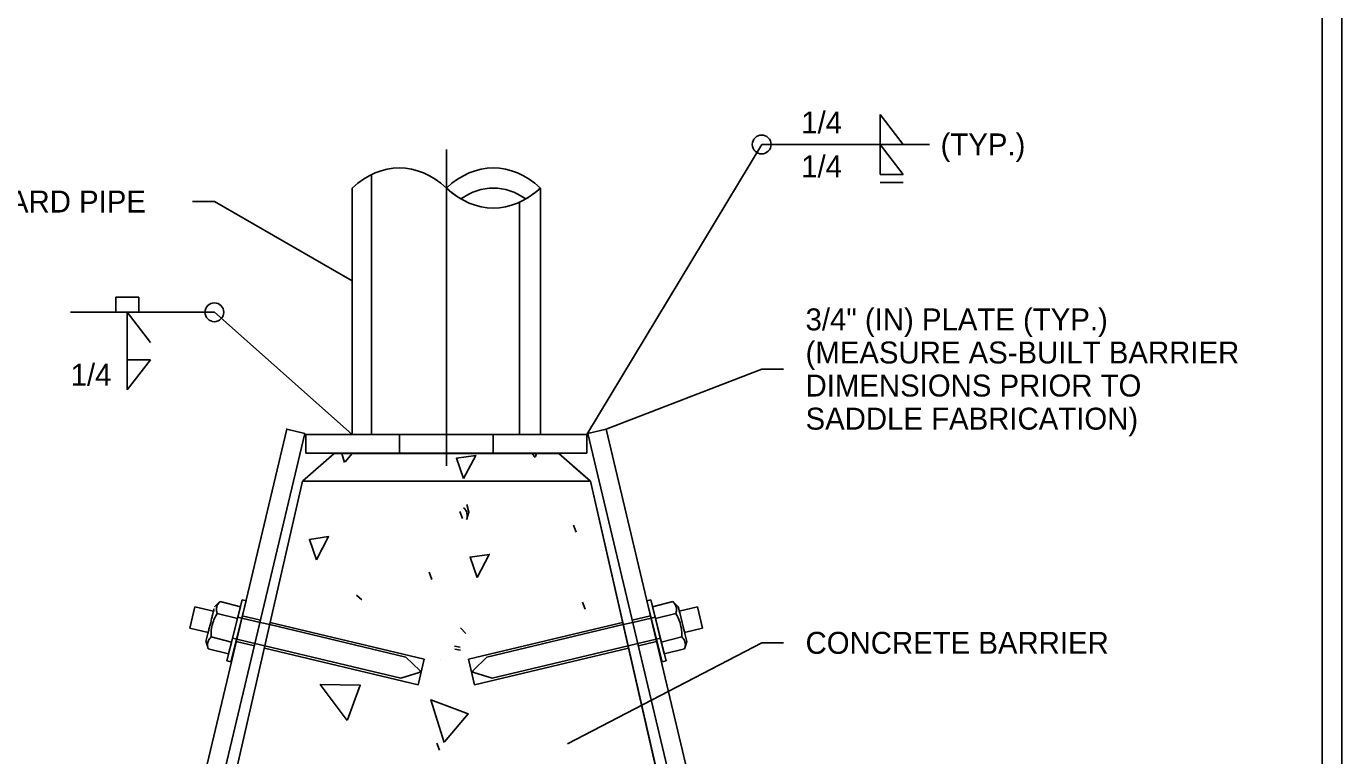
# Model space of a CAD drawing. Extents: x 99988 to 100172, y 99995 to 100047.
# Drawn here: x 100031.616 to 100035.812, y 100003.415 to 100005.742 of the extents above; entities that cross this region are included whole.
import ezdxf

# ---------------------------------------------------------------- set-up
doc = ezdxf.new("R2010")
doc.units = 0
for name, color, linetype in [('Level 1', 7, 'Continuous'), ('Level 10', 7, 'Continuous'), ('Level 12', 7, 'Continuous'), ('Level 15', 7, 'Continuous'), ('Level 18', 7, 'Continuous'), ('Level 20', 7, 'Continuous'), ('Level 24', 7, 'Continuous'), ('Level 51', 7, 'Continuous'), ('Level 8', 7, 'Continuous'), ('SH_GI_PlotLimits', 7, 'Continuous'), ('SH_GI_SheetBorder', 7, 'Continuous'), ('SH_RS_ConstructionNoteFlag', 7, 'Continuous'), ('SH_RS_DimensionLines', 7, 'Continuous')]:
    doc.layers.add(name, color=color, linetype=linetype)

msp = doc.modelspace()

# ---------------------------------------------------------------- linework, layer by layer
at = {"layer": 'Level 1'}
for p, q in [((100033.9621, 100005.3648), (100034.4979, 100005.3648)), ((100034.3401, 100005.2689), (100034.4138, 100005.2689)), ((100034.3401, 100005.2439), (100034.4138, 100005.2439)), ((100032.216, 100004.8293), (100031.7575, 100004.8293))]:
    msp.add_line(p, q, dxfattribs=at)
for centre in [(100033.9621, 100005.3648), (100032.216, 100004.8293)]:
    msp.add_circle(centre, 0.03, dxfattribs=at)
at = {"layer": 'Level 10'}
for p, q in [((100033.028, 100004.1913), (100033.0217, 100004.2164)), ((100032.234, 100003.9067), (100032.2168, 100003.8895)), ((100032.2992, 100003.8902), (100032.2342, 100003.9064)), ((100032.3048, 100003.9125), (100032.2559, 100003.7172)), ((100032.2685, 100003.714), (100032.3174, 100003.9093)), ((100032.2992, 100003.8902), (100032.2897, 100003.8523)), ((100032.299, 100003.8904), (100032.2989, 100003.8902)), ((100032.3174, 100003.9093), (100032.3048, 100003.9125)), ((100033.5954, 100003.9093), (100033.608, 100003.9125)), ((100033.6443, 100003.714), (100033.5954, 100003.9093)), ((100033.608, 100003.9125), (100033.6569, 100003.7172)), ((100033.6136, 100003.8902), (100033.6786, 100003.9064)), ((100033.6136, 100003.8902), (100033.6231, 100003.8523)), ((100033.6138, 100003.8904), (100033.6139, 100003.8902)), ((100033.6788, 100003.9067), (100033.696, 100003.8895)), ((100032.2897, 100003.8523), (100032.2247, 100003.8686)), ((100032.2707, 100003.7764), (100032.2898, 100003.8528)), ((100032.2897, 100003.8523), (100032.2709, 100003.7773)), ((100032.3052, 100003.8608), (100032.3634, 100003.8469)), ((100032.3942, 100003.8396), (100032.8859, 100003.7227)), ((100033.5186, 100003.8396), (100033.0269, 100003.7227)), ((100033.6076, 100003.8608), (100033.5494, 100003.8469)), ((100033.6421, 100003.7764), (100033.623, 100003.8528)), ((100033.6231, 100003.8523), (100033.6881, 100003.8686)), ((100033.6231, 100003.8523), (100033.6419, 100003.7773)), ((100032.1892, 100003.7792), (100032.1955, 100003.8044)), ((100033.0014, 100003.8222), (100033.0187, 100003.805)), ((100033.7236, 100003.7792), (100033.7174, 100003.8044)), ((100032.2615, 100003.7395), (100032.1965, 100003.7558)), ((100032.2709, 100003.7773), (100032.2059, 100003.7936)), ((100032.2709, 100003.7773), (100032.2615, 100003.7395)), ((100032.2615, 100003.7395), (100032.2707, 100003.7764)), ((100032.2859, 100003.7793), (100032.344, 100003.7655)), ((100032.3755, 100003.758), (100032.8665, 100003.6413)), ((100033.5373, 100003.758), (100033.0463, 100003.6413)), ((100033.6269, 100003.7793), (100033.5688, 100003.7655)), ((100033.6419, 100003.7773), (100033.7069, 100003.7936)), ((100033.6419, 100003.7773), (100033.6514, 100003.7395)), ((100033.6514, 100003.7395), (100033.6421, 100003.7764)), ((100033.6514, 100003.7395), (100033.7163, 100003.7558)), ((100032.2559, 100003.7172), (100032.2685, 100003.714)), ((100032.8859, 100003.7227), (100032.8665, 100003.6413)), ((100032.9365, 100003.7209), (100032.9365, 100003.7207)), ((100033.0269, 100003.7227), (100033.0463, 100003.6413)), ((100033.6569, 100003.7172), (100033.6443, 100003.714))]:
    msp.add_line(p, q, dxfattribs=at)
for points, degree in [([(100033.0207, 100004.1678), (100033.0229, 100004.1749), (100033.0237, 100004.1818), (100033.0205, 100004.1947), (100033.0165, 100004.2004), (100033.0112, 100004.2056)], 3), ([(100033.0207, 100004.1678), (100033.0229, 100004.1749), (100033.0237, 100004.1818), (100033.0205, 100004.1947), (100033.0165, 100004.2004), (100033.0112, 100004.2056)], 3), ([(100033.021, 100004.1684), (100033.0233, 100004.176), (100033.0257, 100004.1836), (100033.028, 100004.1913)], 2), ([(100032.1955, 100003.8044), (100032.1955, 100003.8044), (100032.2141, 100003.8789), (100032.2168, 100003.8895), (100032.2141, 100003.8789), (100032.1955, 100003.8044), (100032.1955, 100003.8044)], 4), ([(100032.2247, 100003.8686), (100032.2226, 100003.8757), (100032.2218, 100003.8826), (100032.225, 100003.8955), (100032.229, 100003.9012), (100032.2342, 100003.9064)], 3), ([(100032.2247, 100003.8686), (100032.2226, 100003.8757), (100032.2218, 100003.8826), (100032.225, 100003.8955), (100032.229, 100003.9012), (100032.2342, 100003.9064)], 3), ([(100033.6881, 100003.8686), (100033.6902, 100003.8757), (100033.6911, 100003.8826), (100033.6878, 100003.8955), (100033.6838, 100003.9012), (100033.6786, 100003.9064)], 3), ([(100033.6881, 100003.8686), (100033.6902, 100003.8757), (100033.6911, 100003.8826), (100033.6878, 100003.8955), (100033.6838, 100003.9012), (100033.6786, 100003.9064)], 3), ([(100033.7174, 100003.8044), (100033.7174, 100003.8044), (100033.7093, 100003.837), (100033.696, 100003.8895)], 3), ([(100032.2059, 100003.7936), (100032.2053, 100003.8068), (100032.2061, 100003.8198), (100032.2125, 100003.8453), (100032.218, 100003.8573), (100032.2247, 100003.8686)], 3), ([(100033.7069, 100003.7936), (100033.7075, 100003.8068), (100033.7067, 100003.8198), (100033.7003, 100003.8453), (100033.6948, 100003.8573), (100033.6881, 100003.8686)], 3), ([(100032.1962, 100003.7563), (100032.1939, 100003.764), (100032.1915, 100003.7716), (100032.1892, 100003.7792)], 2), ([(100032.1965, 100003.7558), (100032.1943, 100003.7629), (100032.1935, 100003.7697), (100032.1967, 100003.7826), (100032.2007, 100003.7884), (100032.2059, 100003.7936)], 3), ([(100032.1965, 100003.7558), (100032.1943, 100003.7629), (100032.1935, 100003.7697), (100032.1967, 100003.7826), (100032.2007, 100003.7884), (100032.2059, 100003.7936)], 3), ([(100033.7163, 100003.7558), (100033.7185, 100003.7629), (100033.7193, 100003.7697), (100033.7161, 100003.7826), (100033.7121, 100003.7884), (100033.7069, 100003.7936)], 3), ([(100033.7163, 100003.7558), (100033.7185, 100003.7629), (100033.7193, 100003.7697), (100033.7161, 100003.7826), (100033.7121, 100003.7884), (100033.7069, 100003.7936)], 3), ([(100033.7166, 100003.7563), (100033.719, 100003.764), (100033.7213, 100003.7716), (100033.7236, 100003.7792)], 2)]:
    msp.add_open_spline(points, degree=degree, dxfattribs=at)
at = {"layer": 'Level 12'}
for p, q in [((100032.5083, 100004.4395), (100033.4041, 100004.4395)), ((100032.5083, 100004.3797), (100032.5083, 100004.4395)), ((100033.4041, 100004.4395), (100033.4041, 100004.3797)), ((100033.4041, 100004.3797), (100032.5083, 100004.3797))]:
    msp.add_line(p, q, dxfattribs=at)
for points in [[(100032.5051, 100004.4431), (100032.0075, 100002.35), (100031.9493, 100002.3638), (100032.447, 100004.4569)], [(100033.4073, 100004.4431), (100033.9049, 100002.35), (100033.9631, 100002.3638), (100033.4655, 100004.4569)]]:
    msp.add_lwpolyline(points, close=True, dxfattribs=at)
at = {"layer": 'Level 15'}
for points in [[(100032.6562, 100004.93), (100032.216, 100005.1827), (100032.146, 100005.1827)], [(100033.4655, 100004.4569), (100033.9621, 100004.6483), (100034.0321, 100004.6483)], [(100033.3428, 100003.4522), (100033.9621, 100003.7748), (100034.0321, 100003.7748)]]:
    msp.add_lwpolyline(points, dxfattribs=at)
at = {"layer": 'Level 18'}
for p, q in [((100032.1542, 100003.8896), (100032.138, 100003.8218)), ((100032.2128, 100003.8757), (100032.1542, 100003.8896)), ((100033.6989, 100003.8754), (100033.7575, 100003.8894)), ((100033.7575, 100003.8894), (100033.7736, 100003.8215)), ((100032.2909, 100003.857), (100032.3036, 100003.854)), ((100032.3036, 100003.854), (100032.3618, 100003.8402)), ((100032.3618, 100003.8402), (100032.3926, 100003.8328)), ((100033.5202, 100003.8328), (100033.551, 100003.8402)), ((100033.6092, 100003.854), (100033.551, 100003.8402)), ((100033.6219, 100003.857), (100033.6092, 100003.854)), ((100032.138, 100003.8218), (100032.1958, 100003.808)), ((100032.3926, 100003.8328), (100032.827, 100003.7296)), ((100033.5202, 100003.8328), (100033.0858, 100003.7296)), ((100033.7736, 100003.8215), (100033.7158, 100003.8078)), ((100032.2739, 100003.7894), (100032.2875, 100003.7861)), ((100032.2875, 100003.7861), (100032.3456, 100003.7723)), ((100032.3456, 100003.7723), (100032.3771, 100003.7648)), ((100032.8109, 100003.6617), (100032.3771, 100003.7648)), ((100033.1019, 100003.6617), (100033.5357, 100003.7648)), ((100033.5357, 100003.7648), (100033.5672, 100003.7723)), ((100033.6253, 100003.7861), (100033.5672, 100003.7723)), ((100033.6389, 100003.7894), (100033.6253, 100003.7861)), ((100032.827, 100003.7296), (100032.8711, 100003.6869)), ((100033.0858, 100003.7296), (100033.0417, 100003.6869)), ((100032.8695, 100003.6799), (100032.8109, 100003.6617)), ((100033.0434, 100003.6799), (100033.1019, 100003.6617))]:
    msp.add_line(p, q, dxfattribs=at)
for centre, start, end in [((100032.8682, 100003.6839), 287.2722, 45.9747), ((100033.0446, 100003.6839), 134.0253, 252.7278)]:
    msp.add_arc(centre, 0.00419, start, end, dxfattribs=at)
at = {"layer": 'Level 24'}
for p, q in [((100032.9562, 100005.3492), (100032.9562, 100004.3395)), ((100032.717, 100005.2698), (100032.717, 100004.4395)), ((100032.6562, 100005.2259), (100032.6562, 100004.4395)), ((100033.2562, 100004.4395), (100033.2562, 100005.2259)), ((100033.19, 100005.1808), (100033.19, 100004.4395)), ((100032.8068, 100004.4395), (100032.8068, 100004.3797)), ((100033.1057, 100004.3797), (100033.1057, 100004.4395)), ((100033.1057, 100004.3797), (100032.8068, 100004.3797))]:
    msp.add_line(p, q, dxfattribs=at)
for centre, major_axis, start_param, end_param in [((100032.8062, 100004.812), (0, -0.4779), 2.617994, 3.665191), ((100033.1062, 100004.812), (0, -0.4779), 2.617994, 3.665191), ((100033.1062, 100004.812), (0, -0.4779), 2.617994, 3.665191), ((100033.1062, 100005.6397), (0, -0.4779), 5.759587, 6.806784), ((100033.1062, 100005.6397), (0, -0.4779), 5.759587, 5.930887), ((100033.1062, 100004.812), (0, -0.4135), 2.731392, 3.551794), ((100033.1062, 100004.812), (0, -0.4135), 2.731392, 3.551794), ((100033.1062, 100005.6397), (0, -0.4779), 0.352298, 0.523599)]:
    msp.add_ellipse(centre, major_axis=major_axis, ratio=0.627761, start_param=start_param, end_param=end_param, dxfattribs=at)
at = {"layer": 'Level 51'}
for p, q in [((100034.3401, 100005.3648), (100034.3401, 100005.4607)), ((100034.3401, 100005.4607), (100034.4138, 100005.3648)), ((100034.3401, 100005.2689), (100034.3401, 100005.3648)), ((100034.3401, 100005.3648), (100034.4138, 100005.2689)), ((100031.9014, 100004.8293), (100031.9014, 100004.8773)), ((100031.975, 100004.8773), (100031.9014, 100004.8773)), ((100031.975, 100004.8293), (100031.975, 100004.8773)), ((100031.9382, 100004.5821), (100031.9382, 100004.8293)), ((100031.9382, 100004.8293), (100032.0119, 100004.7334)), ((100031.9382, 100004.5821), (100032.0119, 100004.6779)), ((100032.0119, 100004.6779), (100031.9382, 100004.6779))]:
    msp.add_line(p, q, dxfattribs=at)
at = {"layer": 'Level 8'}
for p, q in [((100032.5982, 100004.379), (100032.4973, 100004.2901)), ((100033.3146, 100004.379), (100032.5982, 100004.379)), ((100033.4155, 100004.2901), (100033.3146, 100004.379)), ((100033.3616, 100004.3376), (100033.3614, 100004.3368)), ((100032.4973, 100004.2901), (100031.9163, 100001.7525)), ((100033.4155, 100004.2901), (100032.4973, 100004.2901)), ((100033.9965, 100001.7525), (100033.4155, 100004.2901)), ((100033.0079, 100004.1715), (100032.9992, 100004.1943)), ((100033.3706, 100004.1277), (100033.3618, 100004.1505)), ((100032.9098, 100003.9771), (100032.901, 100003.9999)), ((100032.6693, 100003.9264), (100032.6868, 100003.9124)), ((100033.3988, 100003.8821), (100033.3901, 100003.9049)), ((100032.9824, 100003.7641), (100033, 100003.7606)), ((100032.9836, 100003.755), (100033.0011, 100003.7515)), ((100032.9345, 100003.432), (100032.9258, 100003.4547))]:
    msp.add_line(p, q, dxfattribs=at)
for points in [[(100033.9965, 100001.7525), (100033.4155, 100004.2901), (100033.3616, 100004.3376), (100033.3146, 100004.379), (100032.5982, 100004.379), (100032.4973, 100004.2901)], [(100032.6312, 100004.3502), (100032.6224, 100004.379)], [(100032.6558, 100004.379), (100032.633, 100004.352)], [(100033.0112, 100004.2989), (100032.9884, 100004.3638), (100033.0497, 100004.3725), (100033.0112, 100004.2989)], [(100033.2392, 100004.3666), (100033.2298, 100004.379)], [(100033.244, 100004.379), (100033.2402, 100004.3688)], [(100032.5419, 100004.0401), (100032.5191, 100004.1049), (100032.5804, 100004.1137), (100032.5419, 100004.0401)], [(100033.0544, 100003.9835), (100033.0316, 100004.0483), (100033.093, 100004.057), (100033.0544, 100003.9835)], [(100032.64, 100003.5273), (100032.5537, 100003.6414), (100032.6813, 100003.6393), (100032.641, 100003.5296)], [(100032.9487, 100003.4569), (100032.9067, 100003.5935), (100033.0258, 100003.548), (100032.9505, 100003.4586)]]:
    msp.add_lwpolyline(points, dxfattribs=at)
at = {"layer": 'SH_GI_PlotLimits'}
msp.add_lwpolyline([(100019.3125, 99999.9375), (100035.8125, 99999.9375), (100035.8125, 100010.4375), (100019.3125, 100010.4375)], close=True, dxfattribs=at)
at = {"layer": 'SH_GI_SheetBorder'}
msp.add_line((100035.75, 100010.375), (100035.75, 100000), dxfattribs=at)
at = {"layer": 'SH_RS_DimensionLines'}
for p, q in [((100033.4041, 100004.4395), (100033.9621, 100005.3648)), ((100032.6562, 100004.4395), (100032.216, 100004.8293))]:
    msp.add_line(p, q, dxfattribs=at)

# ---------------------------------------------------------------- texts
at = {"layer": 'Level 20'}
msp.add_text('5" (IN) DIAM. STANDARD PIPE', height=0.07, dxfattribs=at).set_placement((100030.6643, 100005.1477))
for s, p in [('3/4" (IN) PLATE (TYP.)', (100034.1021, 100004.7717)), ('(MEASURE AS-BUILT BARRIER', (100034.1021, 100004.6661)), ('DIMENSIONS PRIOR TO', (100034.1021, 100004.5606)), ('SADDLE FABRICATION)', (100034.1021, 100004.455)), ('CONCRETE BARRIER', (100034.1021, 100003.7398))]:
    msp.add_text(s, height=0.07, rotation=360, dxfattribs=at).set_placement(p)
at = {"layer": 'SH_RS_ConstructionNoteFlag'}
msp.add_text('1/4', height=0.07, rotation=360, dxfattribs=at).set_placement((100034.0883, 100005.3998))
for s, p in [('(TYP.)', (100034.5329, 100005.3298)), ('1/4', (100034.0883, 100005.2598)), ('1/4', (100031.7575, 100004.595))]:
    msp.add_text(s, height=0.07, dxfattribs=at).set_placement(p)

doc.saveas('drawing.dxf')
